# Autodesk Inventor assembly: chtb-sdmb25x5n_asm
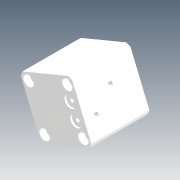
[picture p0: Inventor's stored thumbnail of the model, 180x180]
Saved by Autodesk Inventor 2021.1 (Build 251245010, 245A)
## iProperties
Company: Microsoft
Created: 2018-05
Part Number: chtb-sdmb25x5n_asm
Description: STEP AP214
Document SubType Name: Assembly
Designer: user
Title: chtb-sdmb25x5n_asm.STEP
Author: Windows
Revision Number: ÈÎºÎ
Sending System: SolidWorks 2015
Preprocessor: SwSTEP 2.0
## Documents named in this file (4)
- D:\Vault_2016\Projekty\Clamptek\Hydraulic\CHTB\CHTB-25\Inventor\chtb-sdmb25x5n\chtb-sdmb25x5n_asm.iam
- D:\Vault_2016\Projekty\Clamptek\Hydraulic\CHTB\CHTB-25\Inventor\chtb-sdmb25x5n\CHTB-25QG.ipt
- D:\Vault_2016\Projekty\Clamptek\Hydraulic\CHTB\CHTB-25\Inventor\chtb-sdmb25x5n\CHTB-SDMB25X5NBT.ipt
- D:\Vault_2016\Projekty\Clamptek\Hydraulic\CHTB\CHTB-25\Inventor\chtb-sdmb25x5n\CHTB-SDMB25X5NHSG.ipt
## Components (3 placed, 3 different names)
1. CHTB-25QG_1
2. CHTB-SDMB25X5NBT_2
3. CHTB-SDMB25X5NHSG_3
